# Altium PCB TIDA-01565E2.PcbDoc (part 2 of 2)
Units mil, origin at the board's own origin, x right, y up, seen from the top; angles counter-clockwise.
Board outline 1450 x 4000 mil, 4 copper layers (Top Layer L1, GND L2, Power L3, Bottom Layer L4), stack 62.4 mil thick; 92 components, 39 nets, 230 pads, 175 vias.
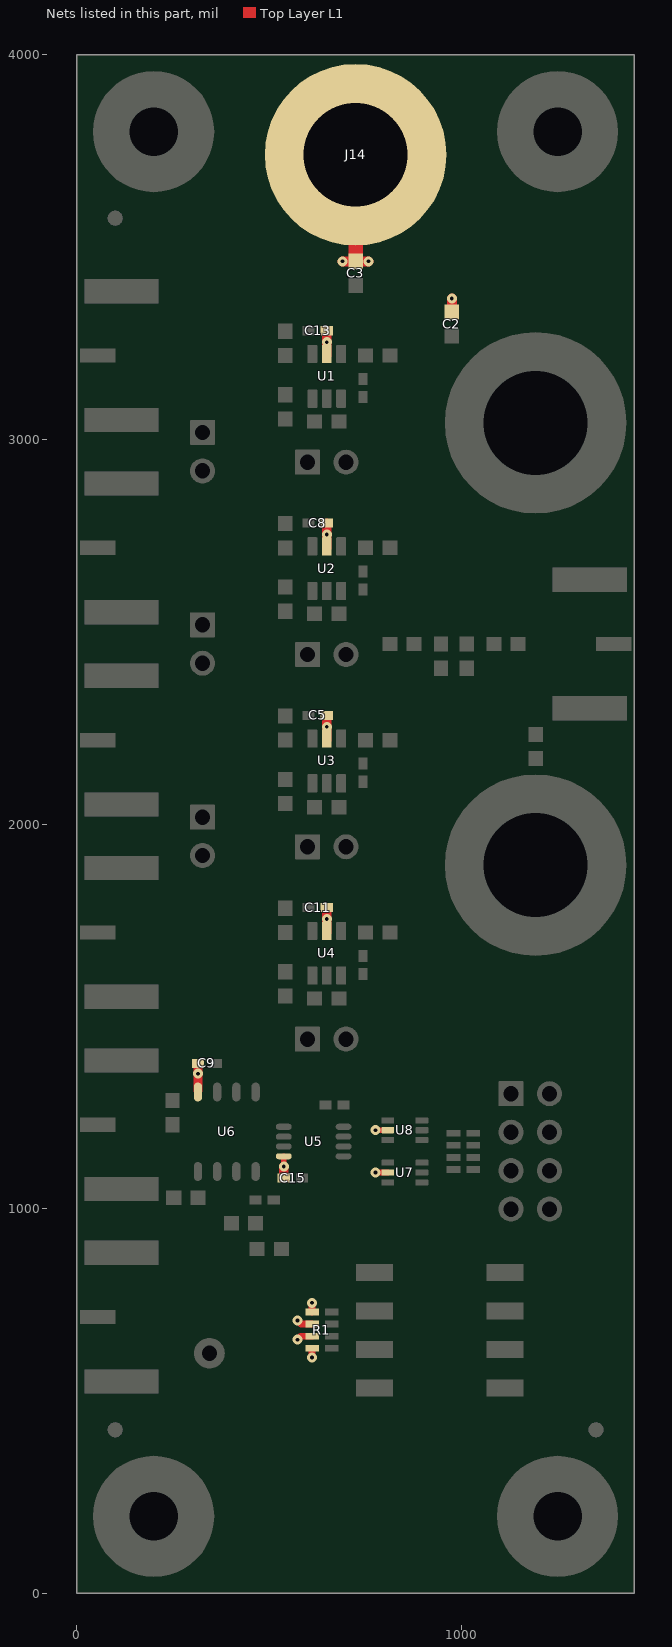
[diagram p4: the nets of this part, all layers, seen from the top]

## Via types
v1: diameter 26, hole 10, Top Layer L1 to Bottom Layer L4, tented both sides, 175 vias

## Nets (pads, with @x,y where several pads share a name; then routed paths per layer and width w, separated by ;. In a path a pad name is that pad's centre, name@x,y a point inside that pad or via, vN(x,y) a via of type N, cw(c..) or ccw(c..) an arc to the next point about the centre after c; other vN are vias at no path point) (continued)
VEE: C2.2 C3.1 C5.1 C8.1 C9.1 C11.1 C13.1 C15.2 J14.1 R1.5 R1.6 R1.7 R1.8 U1.2 U2.2 U3.2 U4.2 U5.4 U6.4 U7.2 U8.2 | length 957.6
  Top Layer L1 w15: v1(538.24,1109.69) U5.4@538.24,1136.02 ; v1(777.01,1093.81) U7.2@808.71,1093.81 ; v1(777.01,1203.81) U8.2@808.71,1203.81
  Top Layer L1 w17.72: v1(574.23,659.11) 583.37,668.25 R1.7@611.91,668.25 ; v1(574.23,708.89) 583.37,699.75 R1.6@611.91,699.75 ; v1(611.91,612.93) R1.8@611.91,636.76 ; R1.5@611.91,731.24 v1(611.91,755.07)
  Top Layer L1 w23.62: U6.4@315,1307.28 C9.1@314.96,1377.57 ; C15.2@538.24,1079.41 v1(538.24,1109.69) ; U4.2@650,1718 v1(650,1752.65) C11.1@650,1782.43 ; U3.2@650,2218 v1(650,2252.65) C5.1@650,2282.43 ; U2.2@650,2718 v1(650,2752.65) C8.1@650,2782.43 ; U1.2@650,3218 v1(650,3252.65) C13.1@650,3282.43
  Top Layer L1 w26: v1(691.33,3463) C3.1@725,3463 v1(758.67,3463) ; C2.2@975,3331.5 v1(975,3366.15)
  Top Layer L1 w37.4: C3.1@725,3463 J14.1@725,3740
  other v1: 315,1350.79
pads on no net: FID1.1 FID2.1 FID3.1 FID4.1 FID5.1 FID6.1 H5.0 H6.0 H7.0 H8.0 LBL1.0

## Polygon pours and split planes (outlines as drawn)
GND on Bottom Layer L4 "Bottom Layer L4-GND" (solid, remove dead copper, pour order 2): 20,20 20,3980 1429.99,3980 1430,20
GND on Top Layer L1 "Top Layer L4-GND" (solid, remove dead copper, pour order 4): 20,20 20,3980 1429.99,3980 1430,20
GND on GND L2 (split plane): 1429.9,20.1 20.1,20.1 20.1,3979.9 1429.9,3979.9
VCC on Power L3 (split plane): 230 vertices, not listed, extent 395.1,20.1 1429.9,3294.9
VEE on Power L3 (split plane): 205 vertices, not listed, extent 20.1,20.1 1429.9,3979.9

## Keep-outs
Keep-Out Layer:
  text ".Layer_Name" at 577,-858.49 h60

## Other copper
Top Layer L1:
  text ".Layer_Name" at 577,-858.49 h60
Bottom Layer L4:
  text ".Layer_Name" at 577,-858.49 h60
GND L2 (plane layer: these items are gaps in the copper):
  pour cut-out: 510.8,1519.35 510.8,1578.72 574.11,1578.72 574.11,1566.88 584.88,1566.88 584.88,1580.69 590.82,1590.69 590.55,1592.06 590.55,1627.41 591.48,1632.09 594.14,1636.07 598.11,1638.72 602.8,1639.65 622.4,1639.65 627.09,1638.72 631.06,1636.07 633.71,1632.09 634.64,1627.41 634.64,1592.06 634.37,1590.69 639.34,1582.41 641.28,1580.69 644.25,1580.69 644.25,1517.39 617.84,1517.39 617.84,1483.48 630.53,1483.48 635.19,1482.55 639.15,1479.91 641.79,1475.96 642.71,1471.29 642.71,1410.46 641.79,1405.57 639.15,1401.62 635.19,1398.97 630.53,1398.05 569.47,1398.05 564.81,1398.97 560.85,1401.62 558.21,1405.57 557.29,1410.23 557.29,1471.29 558.21,1475.96 560.85,1479.91 564.81,1482.55 569.47,1483.48 582.16,1483.48 582.16,1514.64 574.11,1519.35
  pour cut-out: 510.8,2019.35 510.8,2078.72 574.11,2078.72 574.11,2066.88 584.88,2066.88 584.88,2080.69 590.82,2090.69 590.55,2092.06 590.55,2127.41 591.48,2132.09 594.14,2136.07 598.11,2138.72 602.8,2139.65 622.4,2139.65 627.09,2138.72 631.06,2136.07 633.71,2132.09 634.64,2127.41 634.64,2092.06 634.37,2090.69 639.34,2082.41 641.28,2080.69 644.25,2080.69 644.25,2017.39 617.84,2017.39 617.84,1983.48 630.53,1983.48 635.19,1982.55 639.15,1979.91 641.79,1975.96 642.71,1971.29 642.71,1910.46 641.79,1905.57 639.15,1901.62 635.19,1898.97 630.53,1898.05 569.47,1898.05 564.81,1898.97 560.85,1901.62 558.21,1905.57 557.29,1910.23 557.29,1971.29 558.21,1975.96 560.85,1979.91 564.81,1982.55 569.47,1983.48 582.16,1983.48 582.16,2014.64 574.11,2019.35
  pour cut-out: 510.8,2519.35 510.8,2578.72 574.11,2578.72 574.11,2566.88 584.88,2566.88 584.88,2580.69 590.82,2590.69 590.55,2592.06 590.55,2627.41 591.48,2632.09 594.14,2636.07 598.11,2638.72 602.8,2639.65 622.4,2639.65 627.09,2638.72 631.06,2636.07 633.71,2632.09 634.64,2627.41 634.64,2592.06 634.37,2590.69 639.34,2582.41 641.28,2580.69 644.25,2580.69 644.25,2517.39 617.84,2517.39 617.84,2483.48 630.53,2483.48 635.19,2482.55 639.15,2479.91 641.79,2475.96 642.71,2471.29 642.71,2410.46 641.79,2405.57 639.15,2401.62 635.19,2398.97 630.53,2398.05 569.47,2398.05 564.81,2398.97 560.85,2401.62 558.21,2405.57 557.29,2410.23 557.29,2471.29 558.21,2475.96 560.85,2479.91 564.81,2482.55 569.47,2483.48 582.16,2483.48 582.16,2514.64 574.11,2519.35
  pour cut-out: 510.8,3019.35 510.8,3078.72 574.11,3078.72 574.11,3066.88 584.88,3066.88 584.88,3080.69 590.82,3090.69 590.55,3092.06 590.55,3127.41 591.48,3132.09 594.14,3136.07 598.11,3138.72 602.8,3139.65 622.4,3139.65 627.09,3138.72 631.06,3136.07 633.71,3132.09 634.64,3127.41 634.64,3092.06 634.37,3090.69 639.34,3082.41 641.28,3080.69 644.25,3080.69 644.25,3017.39 617.84,3017.39 617.84,2983.48 630.53,2983.48 635.19,2982.55 639.15,2979.91 641.79,2975.96 642.71,2971.29 642.71,2910.46 641.79,2905.57 639.15,2901.62 635.19,2898.98 630.53,2898.05 569.47,2898.05 564.81,2898.98 560.85,2901.62 558.21,2905.57 557.29,2910.23 557.29,2971.29 558.21,2975.96 560.85,2979.91 564.81,2982.55 569.47,2983.48 582.16,2983.48 582.16,3014.64 574.11,3019.35
  pour cut-out: 721.26,1700.16 721.26,1689.3 780.63,1689.3 780.63,1746.7 721.26,1746.7 721.26,1735.84 709.41,1735.84 708.52,1740.36 705.86,1744.33 701.89,1746.99 697.2,1747.92 677.6,1747.92 672.91,1746.99 668.94,1744.33 666.29,1740.36 665.36,1735.68 665.36,1700.32 666.29,1695.64 668.94,1691.67 672.91,1689.01 677.6,1688.08 697.2,1688.08 701.89,1689.01 705.86,1691.67 708.52,1695.64 709.41,1700.16
  pour cut-out: 721.26,2200.16 721.26,2189.3 780.63,2189.3 780.63,2246.7 721.26,2246.7 721.26,2235.84 709.41,2235.84 708.52,2240.36 705.86,2244.33 701.89,2246.99 697.2,2247.92 677.6,2247.92 672.91,2246.99 668.94,2244.33 666.29,2240.36 665.36,2235.68 665.36,2200.32 666.29,2195.64 668.94,2191.67 672.91,2189.01 677.6,2188.08 697.2,2188.08 701.89,2189.01 705.86,2191.67 708.52,2195.64 709.41,2200.16
  pour cut-out: 721.26,2700.16 721.26,2689.3 780.63,2689.3 780.63,2746.7 721.26,2746.7 721.26,2735.84 709.41,2735.84 708.52,2740.36 705.86,2744.33 701.89,2746.99 697.2,2747.92 677.6,2747.92 672.91,2746.99 668.94,2744.33 666.29,2740.36 665.36,2735.68 665.36,2700.32 666.29,2695.64 668.94,2691.67 672.91,2689.01 677.6,2688.08 697.2,2688.08 701.89,2689.01 705.86,2691.67 708.52,2695.64 709.41,2700.16
  pour cut-out: 721.26,3200.16 721.26,3189.3 780.63,3189.3 780.63,3246.7 721.26,3246.7 721.26,3235.84 709.41,3235.84 708.52,3240.36 705.86,3244.33 701.89,3246.99 697.2,3247.92 677.6,3247.92 672.91,3246.99 668.94,3244.33 666.29,3240.36 665.36,3235.68 665.36,3200.32 666.29,3195.64 668.94,3191.67 672.91,3189.01 677.6,3188.08 697.2,3188.08 701.89,3189.01 705.86,3191.67 708.52,3195.64 709.41,3200.16
  text "GND" at 700,50 h60
  text ".Layer_Name" at 577,-858.49 h60
Power L3 (plane layer: these items are gaps in the copper):
  pour cut-out: 721.26,3200.16 721.26,3189.3 780.63,3189.3 780.63,3246.7 721.26,3246.7 721.26,3235.84 709.41,3235.84 708.52,3240.36 705.86,3244.33 701.89,3246.99 697.2,3247.92 677.6,3247.92 672.91,3246.99 668.94,3244.33 666.29,3240.36 665.36,3235.68 665.36,3200.32 666.29,3195.64 668.94,3191.67 672.91,3189.01 677.6,3188.08 697.2,3188.08 701.89,3189.01 705.86,3191.67 708.52,3195.64 709.41,3200.16
  pour cut-out: 721.26,2700.16 721.26,2689.3 780.63,2689.3 780.63,2746.7 721.26,2746.7 721.26,2735.84 709.41,2735.84 708.52,2740.36 705.86,2744.33 701.89,2746.99 697.2,2747.92 677.6,2747.92 672.91,2746.99 668.94,2744.33 666.29,2740.36 665.36,2735.68 665.36,2700.32 666.29,2695.64 668.94,2691.67 672.91,2689.01 677.6,2688.08 697.2,2688.08 701.89,2689.01 705.86,2691.67 708.52,2695.64 709.41,2700.16
  pour cut-out: 721.26,2200.16 721.26,2189.3 780.63,2189.3 780.63,2246.7 721.26,2246.7 721.26,2235.84 709.41,2235.84 708.52,2240.36 705.86,2244.33 701.89,2246.99 697.2,2247.92 677.6,2247.92 672.91,2246.99 668.94,2244.33 666.29,2240.36 665.36,2235.68 665.36,2200.32 666.29,2195.64 668.94,2191.67 672.91,2189.01 677.6,2188.08 697.2,2188.08 701.89,2189.01 705.86,2191.67 708.52,2195.64 709.41,2200.16
  pour cut-out: 721.26,1700.16 721.26,1689.3 780.63,1689.3 780.63,1746.7 721.26,1746.7 721.26,1735.84 709.41,1735.84 708.52,1740.36 705.86,1744.33 701.89,1746.99 697.2,1747.92 677.6,1747.92 672.91,1746.99 668.94,1744.33 666.29,1740.36 665.36,1735.68 665.36,1700.32 666.29,1695.64 668.94,1691.67 672.91,1689.01 677.6,1688.08 697.2,1688.08 701.89,1689.01 705.86,1691.67 708.52,1695.64 709.41,1700.16
  pour cut-out: 510.8,3019.35 510.8,3078.72 574.11,3078.72 574.11,3066.88 584.88,3066.88 584.88,3080.69 590.82,3090.69 590.55,3092.06 590.55,3127.41 591.48,3132.09 594.14,3136.07 598.11,3138.72 602.8,3139.65 622.4,3139.65 627.09,3138.72 631.06,3136.07 633.71,3132.09 634.64,3127.41 634.64,3092.06 634.37,3090.69 639.34,3082.41 641.28,3080.69 644.25,3080.69 644.25,3017.39 617.84,3017.39 617.84,2983.48 630.53,2983.48 635.19,2982.55 639.15,2979.91 641.79,2975.96 642.71,2971.29 642.71,2910.46 641.79,2905.57 639.15,2901.62 635.19,2898.98 630.53,2898.05 569.47,2898.05 564.81,2898.98 560.85,2901.62 558.21,2905.57 557.29,2910.23 557.29,2971.29 558.21,2975.96 560.85,2979.91 564.81,2982.55 569.47,2983.48 582.16,2983.48 582.16,3014.64 574.11,3019.35
  pour cut-out: 510.8,2519.35 510.8,2578.72 574.11,2578.72 574.11,2566.88 584.88,2566.88 584.88,2580.69 590.82,2590.69 590.55,2592.06 590.55,2627.41 591.48,2632.09 594.14,2636.07 598.11,2638.72 602.8,2639.65 622.4,2639.65 627.09,2638.72 631.06,2636.07 633.71,2632.09 634.64,2627.41 634.64,2592.06 634.37,2590.69 639.34,2582.41 641.28,2580.69 644.25,2580.69 644.25,2517.39 617.84,2517.39 617.84,2483.48 630.53,2483.48 635.19,2482.55 639.15,2479.91 641.79,2475.96 642.71,2471.29 642.71,2410.46 641.79,2405.57 639.15,2401.62 635.19,2398.97 630.53,2398.05 569.47,2398.05 564.81,2398.97 560.85,2401.62 558.21,2405.57 557.29,2410.23 557.29,2471.29 558.21,2475.96 560.85,2479.91 564.81,2482.55 569.47,2483.48 582.16,2483.48 582.16,2514.64 574.11,2519.35
  pour cut-out: 510.8,2019.35 510.8,2078.72 574.11,2078.72 574.11,2066.88 584.88,2066.88 584.88,2080.69 590.82,2090.69 590.55,2092.06 590.55,2127.41 591.48,2132.09 594.14,2136.07 598.11,2138.72 602.8,2139.65 622.4,2139.65 627.09,2138.72 631.06,2136.07 633.71,2132.09 634.64,2127.41 634.64,2092.06 634.37,2090.69 639.34,2082.41 641.28,2080.69 644.25,2080.69 644.25,2017.39 617.84,2017.39 617.84,1983.48 630.53,1983.48 635.19,1982.55 639.15,1979.91 641.79,1975.96 642.71,1971.29 642.71,1910.46 641.79,1905.57 639.15,1901.62 635.19,1898.97 630.53,1898.05 569.47,1898.05 564.81,1898.97 560.85,1901.62 558.21,1905.57 557.29,1910.23 557.29,1971.29 558.21,1975.96 560.85,1979.91 564.81,1982.55 569.47,1983.48 582.16,1983.48 582.16,2014.64 574.11,2019.35
  pour cut-out: 510.8,1519.35 510.8,1578.72 574.11,1578.72 574.11,1566.88 584.88,1566.88 584.88,1580.69 590.82,1590.69 590.55,1592.06 590.55,1627.41 591.48,1632.09 594.14,1636.07 598.11,1638.72 602.8,1639.65 622.4,1639.65 627.09,1638.72 631.06,1636.07 633.71,1632.09 634.64,1627.41 634.64,1592.06 634.37,1590.69 639.34,1582.41 641.28,1580.69 644.25,1580.69 644.25,1517.39 617.84,1517.39 617.84,1483.48 630.53,1483.48 635.19,1482.55 639.15,1479.91 641.79,1475.96 642.71,1471.29 642.71,1410.46 641.79,1405.57 639.15,1401.62 635.19,1398.97 630.53,1398.05 569.47,1398.05 564.81,1398.97 560.85,1401.62 558.21,1405.57 557.29,1410.23 557.29,1471.29 558.21,1475.96 560.85,1479.91 564.81,1482.55 569.47,1483.48 582.16,1483.48 582.16,1514.64 574.11,1519.35
  lines w10: 637.5,0 637.5,834 390,834 390,1137 499.65,1137 499.65,1050.92 802,1050.92 802,1229 753,1229 753,1200 612.6,1200 612.6,1639.06 687.4,1713.87 687.4,1800 612.6,1874.8 612.6,2139.06 687.4,2213.87 687.4,2300 612.6,2374.8 612.6,2639.06 687.4,2713.87 687.4,2800 612.6,2874.8 612.6,3139.06 687.4,3213.87 687.4,3300 1450,3300
  text "VEE" at 425,50 h60
  text "VCC" at 900,50 h60
  text ".Layer_Name" at 577,-858.49 h60
Multi-Layer:
  pour cut-out: 721.26,3200.16 721.26,3189.3 780.63,3189.3 780.63,3246.7 721.26,3246.7 721.26,3235.84 709.41,3235.84 708.52,3240.36 705.86,3244.33 701.89,3246.99 697.2,3247.92 677.6,3247.92 672.91,3246.99 668.94,3244.33 666.29,3240.36 665.36,3235.68 665.36,3200.32 666.29,3195.64 668.94,3191.67 672.91,3189.01 677.6,3188.08 697.2,3188.08 701.89,3189.01 705.86,3191.67 708.52,3195.64 709.41,3200.16
  pour cut-out: 721.26,2700.16 721.26,2689.3 780.63,2689.3 780.63,2746.7 721.26,2746.7 721.26,2735.84 709.41,2735.84 708.52,2740.36 705.86,2744.33 701.89,2746.99 697.2,2747.92 677.6,2747.92 672.91,2746.99 668.94,2744.33 666.29,2740.36 665.36,2735.68 665.36,2700.32 666.29,2695.64 668.94,2691.67 672.91,2689.01 677.6,2688.08 697.2,2688.08 701.89,2689.01 705.86,2691.67 708.52,2695.64 709.41,2700.16
  pour cut-out: 721.26,2200.16 721.26,2189.3 780.63,2189.3 780.63,2246.7 721.26,2246.7 721.26,2235.84 709.41,2235.84 708.52,2240.36 705.86,2244.33 701.89,2246.99 697.2,2247.92 677.6,2247.92 672.91,2246.99 668.94,2244.33 666.29,2240.36 665.36,2235.68 665.36,2200.32 666.29,2195.64 668.94,2191.67 672.91,2189.01 677.6,2188.08 697.2,2188.08 701.89,2189.01 705.86,2191.67 708.52,2195.64 709.41,2200.16
  pour cut-out: 721.26,1700.16 721.26,1689.3 780.63,1689.3 780.63,1746.7 721.26,1746.7 721.26,1735.84 709.41,1735.84 708.52,1740.36 705.86,1744.33 701.89,1746.99 697.2,1747.92 677.6,1747.92 672.91,1746.99 668.94,1744.33 666.29,1740.36 665.36,1735.68 665.36,1700.32 666.29,1695.64 668.94,1691.67 672.91,1689.01 677.6,1688.08 697.2,1688.08 701.89,1689.01 705.86,1691.67 708.52,1695.64 709.41,1700.16
  pour cut-out: 510.8,3019.35 510.8,3078.72 574.11,3078.72 574.11,3066.88 584.88,3066.88 584.88,3080.69 590.82,3090.69 590.55,3092.06 590.55,3127.41 591.48,3132.09 594.14,3136.07 598.11,3138.72 602.8,3139.65 622.4,3139.65 627.09,3138.72 631.06,3136.07 633.71,3132.09 634.64,3127.41 634.64,3092.06 634.37,3090.69 639.34,3082.41 641.28,3080.69 644.25,3080.69 644.25,3017.39 617.84,3017.39 617.84,2983.48 630.53,2983.48 635.19,2982.55 639.15,2979.91 641.79,2975.96 642.71,2971.29 642.71,2910.46 641.79,2905.57 639.15,2901.62 635.19,2898.98 630.53,2898.05 569.47,2898.05 564.81,2898.98 560.85,2901.62 558.21,2905.57 557.29,2910.23 557.29,2971.29 558.21,2975.96 560.85,2979.91 564.81,2982.55 569.47,2983.48 582.16,2983.48 582.16,3014.64 574.11,3019.35
  pour cut-out: 510.8,2519.35 510.8,2578.72 574.11,2578.72 574.11,2566.88 584.88,2566.88 584.88,2580.69 590.82,2590.69 590.55,2592.06 590.55,2627.41 591.48,2632.09 594.14,2636.07 598.11,2638.72 602.8,2639.65 622.4,2639.65 627.09,2638.72 631.06,2636.07 633.71,2632.09 634.64,2627.41 634.64,2592.06 634.37,2590.69 639.34,2582.41 641.28,2580.69 644.25,2580.69 644.25,2517.39 617.84,2517.39 617.84,2483.48 630.53,2483.48 635.19,2482.55 639.15,2479.91 641.79,2475.96 642.71,2471.29 642.71,2410.46 641.79,2405.57 639.15,2401.62 635.19,2398.97 630.53,2398.05 569.47,2398.05 564.81,2398.97 560.85,2401.62 558.21,2405.57 557.29,2410.23 557.29,2471.29 558.21,2475.96 560.85,2479.91 564.81,2482.55 569.47,2483.48 582.16,2483.48 582.16,2514.64 574.11,2519.35
  pour cut-out: 510.8,2019.35 510.8,2078.72 574.11,2078.72 574.11,2066.88 584.88,2066.88 584.88,2080.69 590.82,2090.69 590.55,2092.06 590.55,2127.41 591.48,2132.09 594.14,2136.07 598.11,2138.72 602.8,2139.65 622.4,2139.65 627.09,2138.72 631.06,2136.07 633.71,2132.09 634.64,2127.41 634.64,2092.06 634.37,2090.69 639.34,2082.41 641.28,2080.69 644.25,2080.69 644.25,2017.39 617.84,2017.39 617.84,1983.48 630.53,1983.48 635.19,1982.55 639.15,1979.91 641.79,1975.96 642.71,1971.29 642.71,1910.46 641.79,1905.57 639.15,1901.62 635.19,1898.97 630.53,1898.05 569.47,1898.05 564.81,1898.97 560.85,1901.62 558.21,1905.57 557.29,1910.23 557.29,1971.29 558.21,1975.96 560.85,1979.91 564.81,1982.55 569.47,1983.48 582.16,1983.48 582.16,2014.64 574.11,2019.35
  pour cut-out: 510.8,1519.35 510.8,1578.72 574.11,1578.72 574.11,1566.88 584.88,1566.88 584.88,1580.69 590.82,1590.69 590.55,1592.06 590.55,1627.41 591.48,1632.09 594.14,1636.07 598.11,1638.72 602.8,1639.65 622.4,1639.65 627.09,1638.72 631.06,1636.07 633.71,1632.09 634.64,1627.41 634.64,1592.06 634.37,1590.69 639.34,1582.41 641.28,1580.69 644.25,1580.69 644.25,1517.39 617.84,1517.39 617.84,1483.48 630.53,1483.48 635.19,1482.55 639.15,1479.91 641.79,1475.96 642.71,1471.29 642.71,1410.46 641.79,1405.57 639.15,1401.62 635.19,1398.97 630.53,1398.05 569.47,1398.05 564.81,1398.97 560.85,1401.62 558.21,1405.57 557.29,1410.23 557.29,1471.29 558.21,1475.96 560.85,1479.91 564.81,1482.55 569.47,1483.48 582.16,1483.48 582.16,1514.64 574.11,1519.35

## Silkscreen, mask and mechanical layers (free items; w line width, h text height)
Top Overlay:
  text "'.PRJ_Number'.PCB_Rev" at 951,3506 h40
  text ".Layer_Name" at 577,-858.49 h60
Bottom Overlay:
  text ".Layer_Name" at 577,-858.49 h60
Top Paste:
  text ".Layer_Name" at 577,-858.49 h60
Bottom Paste:
  text ".Layer_Name" at 577,-858.49 h60
Top Solder:
  text ".Layer_Name" at 577,-858.49 h60
  text ".Layer_Name" at 577,-858.49 h60
Bottom Solder:
  text ".Layer_Name" at 577,-858.49 h60
Drill Guide:
  text ".Layer_Name" at 577,-858.49 h60
M1 Board Outline:
  the board outline again, w10
  text ".Layer_Name" at 577,-858.49 h60
M2 Board Dimensions:
  rectangle: 125,-400 500,-275
  rectangle: 0,-275 125,-150
  lines w7: 0,-275 1000,-275 ; 125,-400 125,-150 ; 250,-400 250,-150 ; 500,-400 500,-150 ; 750,-400 750,-150 ; 0,-400 0,-150 1000,-150 1000,-400 0,-400
  text ".Layer_Name" at 577,-858.49 h60
M3 3D STEP Top:
  text ".Layer_Name" at 577,-858.49 h60
M4 3D STEP Bottom:
  text ".Layer_Name" at 577,-858.49 h60
M5 Assembly Top:
  lines w10: -292,-930.17 6308,-930.17 ; -292,-726.83 6310,-726.83 ; -292,-523.5 -292,-1133.5 3713,-1133.5 6310,-1133.5 6310,-523.5 -291.5,-523.5 -291.5,-1133.5 1284,-1133.5 ; 2173,-1133.5 2173,-523.5 ; 3440,-726.83 3440,-523.5 ; 4280,-726.83 4280,-523.5 ; 4902,-1140 4902,-937.17
  text "COMPONENTS MARKED 'DNP' SHOULD NOT BE POPULATED." at 1153.5,-318.5 h60
  text "ASSEMBLY VARIANT:" at 1153,-434 h60
  text ".VariantName" at 2189,-434 h60
  text "PCB VIEWED FROM TOP SIDE" at -228.5,-655.67 h60
  text "BOARD #:" at 2248,-655.67 h60
  text ".PRJ_Number" at 2793.5,-655.67 h60
  text "REV:" at 3638,-655.67 h60
  text ".PCB_Rev" at 3929.5,-655.67 h60
  text "SVN REV:" at 4476,-655.67 h60
  text ".VersionControl_RevNumber" at 4982,-655.67 h60
  text "TID #:" at 2248,-859 h60
  text ".TID" at 2793.5,-859 h60
  text "PLOT NAME =" at -228.5,-1064.34 h60
  text ".plot_File_Name" at 577,-1064.34 h60
  text "GENERATED    :" at 2250,-1064.34 h60
  text ".Print_Date" at 3119.5,-1064.34 h60
  text ".Print_Time" at 3848.5,-1064.34 h60
  text "TEXAS INSTRUMENTS" at 5113,-1064.34 h60
M6 Assembly Bottom:
  lines w10: -292.5,-727.33 6309.5,-727.33 ; -290.5,-930.67 6309.5,-930.67 ; 1115.5,-1140.5 1115.5,-937.67 ; 1737.5,-727.33 1737.5,-524 ; 2577.5,-727.33 2577.5,-524 ; 3844.5,-1134 3844.5,-524 ; 4733.5,-1134 6309,-1134 6309,-524 -292.5,-524 -292.5,-1134 2304.5,-1134 6309.5,-1134 6309.5,-524
  text "COMPONENTS MARKED 'DNP' SHOULD NOT BE POPULATED." at 6102,-318 h60
  text ".VariantName" at 5058,-434 h60
  text "ASSEMBLY VARIANT:" at 6097,-434 h60
  text ".VersionControl_RevNumber" at 1035.5,-656.17 h60
  text "SVN REV:" at 1541.5,-656.17 h60
  text ".PCB_Rev" at 2088,-656.17 h60
  text "REV:" at 2379.5,-656.17 h60
  text ".PRJ_Number" at 3224,-656.17 h60
  text "BOARD #:" at 3769.5,-656.17 h60
  text "PCB VIEWED FROM BOTTOM SIDE" at 6246,-656.17 h60
  text ".TID" at 3224,-859.5 h60
  text "TID #:" at 3769.5,-859.5 h60
  text "TEXAS INSTRUMENTS" at 904.5,-1064.84 h60
  text ".Print_Time" at 2169,-1064.84 h60
  text ".Print_Date" at 2898,-1064.84 h60
  text "GENERATED    :" at 3767.5,-1064.84 h60
  text ".plot_File_Name" at 5440.5,-1064.84 h60
  text "PLOT NAME =" at 6246,-1064.84 h60
M9 Title Sheet:
  drawing of 57 lines, arcs and shapes, not listed
  text "1" at 739.84,8036.5 h70
  text "2" at 3235.5,8036.5 h70
  text "3" at 5724.84,8036.5 h70
  text "4" at 8231.51,8036.5 h70
  text "5" at 10730.5,8036.5 h70
  text "6" at 13235.5,8036.5 h70
  text "A" at -416.5,6893.5 h70
  text "A" at 14383.5,6893.5 h70
  text "B" at -416.5,4513.5 h70
  text "B" at 14383.5,4513.5 h70
  text "C" at -416.5,2138.5 h70
  text "C" at 14383.5,2138.5 h70
  text "PROJECT TITLE:" at 11343.5,277.5 h45
  text ".PRJ_Title" at 11393.5,144.17 h70
  text "DESIGNED FOR:" at 11343.5,-23.5 h45
  text ".PRJ_Customer" at 11393.5,-163.5 h70
  text "D" at -416.5,-231.5 h70
  text "D" at 14383.5,-231.5 h70
  text "FILE NAME:" at 11343.5,-323.5 h45
  text ".PCB_File_Name_No_Path" at 11393.5,-443.5 h70
  text "Texas Instruments (TI) and/or its licensors do not warrant the accuracy or completeness of this specification" at 6374,-605.34 h45
  text "ENGINEER:" at 11343.5,-613.5 h45
  text "LAYOUT BY:" at 12848.5,-613.5 h45
  text "or any information contained therein. TI and/or its licensors do not warrant that this design will meet" at 6329.01,-718 h45
  text ".PRJ_Engineer" at 11393.5,-768.49 h70
  text ".PCB_Layout" at 12899,-768.49 h70
  text "the specifications, will be suitable for your application or fit for any particular purpose, or will operate in" at 6329.01,-830.67 h45
  text ".Layer_Name" at 577,-858.49 h60
  text "ALTIUM DESIGNER VERSION:" at 12848.5,-923.5 h45
  text "an implementation. TI and/or its licensors do not warrant that the design is production worthy. You should" at 6329.01,-943.33 h45
  text "completely validate and test your design implementation to confirm the system functionality for your application." at 6374,-1056 h45
  text ".print_Scale" at 11393.5,-1056.83 h70
  text ".Application_BuildNumber" at 12899,-1056.83 h70
  text "1" at 739.84,-1263.5 h70
  text "2" at 3235.5,-1263.5 h70
  text "3" at 5724.84,-1263.5 h70
  text "4" at 8231.51,-1263.5 h70
  text "5" at 10730.5,-1263.5 h70
  text "6" at 13235.5,-1263.5 h70
M10 Fab Notes:
  drawing of 173 lines, arcs and shapes, not listed
  text "DESIGN INFORMATION" at 12378.02,6201 h60
  text "MIN. TRACK WIDTH:" at 11733.46,6021 h60
  text "8" at 12829.7,6021 h60
  text "MIL" at 12984.46,6021 h60
  text "MIN. CLEARANCE:" at 11733.46,5889 h60
  text "0.2" at 12769.7,5889 h60
  text "mm" at 12984.46,5889 h60
  text "MIN. VIA PAD SIZE:" at 11733.46,5757 h60
  text "24" at 12799.71,5757 h60
  text "MIL" at 12984.46,5757 h60
  text "0.05mm (2MIL)" at 12428.46,5615.29 h60
  text "MINIMUM ANNULAR RING" at 11404.23,5611 h60
  text "EXTERNAL" at 13136.46,5611 h60
  text "PER" at 11604.23,5493 h60
  text "IPC-D-275 CLASS 2 LEVEL C" at 11824.23,5493 h60
  text "MIL, HOLES" at 13312.46,5380.71 h60
  text "+/-" at 12920,5380 h60
  text "+/-" at 13774,5380 h60
  text "REGISTRATION TOLERANCES:" at 11404.23,5375 h60
  text "METAL" at 12604,5375 h60
  text "5" at 13180.2,5375 h60
  text "3" at 14013.2,5375 h60
  text "MIL" at 14129.46,5375 h60
  text "+/-" at 13774,5262 h60
  text "HOLE SIZE TOLERANCE (UNLESS OTHERWISE SPECIFIED):" at 11404.23,5257 h60
  text "3" at 14013.2,5257 h60
  text "MIL" at 14129.46,5257 h60
  text "MATERIAL:" at 11329.46,5047.54 h60
  text "FR-4 High Tg" at 12315.9,4907.21 h60
  text "FR-408" at 11750.46,4898.64 h60
  text "OTHER" at 13238.46,4898.64 h60
  text "X" at 12161,4895 h60
  text "62 MIL (1.6mm) +/-10%" at 12070.56,4735.92 h60
  text "THICKNESS:" at 11404.23,4731.64 h60
  text "X" at 11942.4,4731.64 h60
  text "OTHER" at 13355.46,4731.64 h60
  text "TOLERANCE:" at 11404.23,4573.64 h60
  text "X" at 12243.53,4573.64 h60
  text "ANSI IPC-6012 TYPE 3 CLASS 2" at 12430.48,4573.64 h60
  text "OTHER +/-" at 12430.46,4417.64 h60
  text "BOW & TWIST:" at 11404.23,4260.64 h60
  text "X" at 12243.53,4260.64 h60
  text "ANSI IPC-6012 TYPE 3 CLASS 2" at 12430.48,4260.64 h60
  text "OTHER +/-" at 12430.46,4102.13 h60
  text "DRILLING:" at 11329.46,3963.64 h60
  text "REFERENCE:" at 11404.23,3846.64 h60
  text "X" at 12052.46,3846.64 h60
  text "AS SHOWN" at 12239.46,3846.64 h60
  text "X" at 12953.46,3846.64 h60
  text "NC_DRILL FILES" at 13090.46,3846.64 h60
  text "PTH COPPER THICKNESS:" at 11404.23,3688.64 h60
  text "X" at 12534.46,3688.64 h60
  text "20-30 um" at 12671.46,3688.64 h60
  text "OTHER" at 13388.46,3688.64 h60
  text "BOARD FINISH:" at 11329.46,3529.64 h60
  text "SILKSCREEN:" at 11484.68,3411.64 h60
  text "X" at 12433.46,3411.64 h60
  text "TOP" at 12559.46,3411.64 h60
  text "BOTTOM" at 13070.46,3411.64 h60
  text "SILKSCREEN COLOR:" at 11484.68,3244.64 h60
  text "X" at 12432.42,3244.64 h60
  text "WHITE" at 12559.46,3244.64 h60
  text "OTHER" at 13070.46,3244.64 h60
  text "X" at 12563.42,3085.44 h60
  text "GREEN" at 12690.46,3085.44 h60
  text "OTHER" at 13308.46,3085.44 h60
  text "SOLDER RESIST COLOR:" at 11484.68,3074.64 h60
  text "X" at 12563.42,2915.44 h60
  text "MATTE" at 12690.46,2915.44 h60
  text "SEMI-GLOSS" at 13308,2914.8 h60
  text "IMMERSION GOLD (ENIG)" at 12390.46,2726.92 h60
  text "ENEPIG" at 13728,2723.64 h60
  text "SURFACE FINISH:" at 11329.46,2722.64 h60
  text "X" at 12203.51,2722.64 h60
  text "IMM. TIN/SILVER OR EQUIV" at 11659,2565.64 h60
  text "OTHER" at 13090.46,2565.64 h60
  text "ARRAY/PANEL:" at 11329.46,2386.64 h60
  text "CUT AND TRIM PER M1 BOARD OUTLINE" at 12390.46,2382.35 h60
  text "N.C. ROUTE" at 12390.46,2230.64 h60
  text "X" at 13069.46,2230.64 h60
  text "V. SCORE" at 13256.46,2230.64 h60
  text "CERTIFICATION:" at 11329.46,2093.64 h60
  text "MATERIALS AND WORKMANSHIP FOR ALL PCBS" at 12054.46,2093.64 h60
  text "TO MEET OR EXCEED THE REQUIREMENTS OF:" at 12054.46,1995.64 h60
  text "X" at 11680.96,1859.13 h60
  text "ANSI IPC-A-600F CLASS ->" at 11819.96,1859.13 h60
  text "X" at 13459.02,1859.13 h60
  text "2" at 13577.96,1859.14 h60
  text "1" at 13262.96,1857.64 h60
  text "3" at 13931.96,1857.64 h60
  text "X" at 12495.02,1699.64 h60
  text "RoHS" at 12631.96,1699.64 h60
  text "OTHER" at 13276.36,1699.64 h60
  text "PER ORDER" at 13673.42,1699.64 h60
  text "ALL BOARDS MUST MEET OR EXCEED UL94-V0 REQUIREMENTS." at 11357,1534 h60
  text "PCB MUST BEAR THE UL94V-0 UL REGISTERED MATERIAL ID NUMBER" at 11357,1414 h60
  text "ADDITIONAL REQUIREMENTS:" at 11329.46,1240.64 h60
  text "MICROSECTION:" at 11404.23,1125.64 h60
  text "YES" at 12309.96,1125.64 h60
  text "REQUIRED" at 13171.46,969.49 h60
  text "BARE BOARD ELEC. TEST:" at 11404.23,966.64 h60
  text "NONE" at 12709.96,966.64 h60
  text "X" at 13044.46,966.64 h60
  text "PER ORDER" at 13763.46,966.64 h60
  text ".Layer_Name" at 577,-858.49 h60
M11 Gerber Information:
  lines w10: -292,-930.17 6308,-930.17 ; -292,-726.83 6310,-726.83 ; -292,-523.5 -292,-1133.5 3713,-1133.5 6310,-1133.5 6310,-523.5 -291.5,-523.5 -291.5,-1133.5 1284,-1133.5 ; 2173,-1133.5 2173,-523.5 ; 3440,-726.83 3440,-523.5 ; 4280,-726.83 4280,-523.5 ; 4902,-1140 4902,-937.17
  text "ALL ARTWORK VIEWED FROM TOP SIDE" at -228.5,-655.67 h60
  text "BOARD #:" at 2248,-655.67 h60
  text ".PRJ_Number" at 2793.5,-655.67 h60
  text "REV:" at 3638,-655.67 h60
  text ".PCB_Rev" at 3929.5,-655.67 h60
  text "SVN REV:" at 4476,-655.67 h60
  text ".VersionControl_RevNumber" at 4982,-655.67 h60
  text "LAYER NAME =" at -228.5,-858.49 h60
  text "TID #:" at 2248,-859 h60
  text ".TID" at 2793.5,-859 h60
  text "PLOT NAME =" at -228.5,-1064.34 h60
  text ".plot_File_Name" at 577,-1064.34 h60
  text "GENERATED    :" at 2250,-1064.34 h60
  text ".Print_Date" at 3119.5,-1064.34 h60
  text ".Print_Time" at 3848.5,-1064.34 h60
  text "TEXAS INSTRUMENTS" at 5113,-1064.34 h60
M12 Stackup:
  drawing of 295 lines, arcs and shapes, not listed
  text "Layer" at 9667.5,7830 h60
  text "Name" at 10077.41,7830 h60
  text "Material" at 11077.13,7830 h60
  text "Thickness" at 11936.9,7830 h60
  text "Constant" at 12586.74,7830 h60
  text "Board Layer Stack" at 13156.6,7830 h60
  text "1" at 9667.5,7710 h60
  text "Top Overlay" at 10077.41,7710 h60
  text "2" at 9667.5,7590 h60
  text "Top Solder" at 10077.41,7590 h60
  text "Solder Resist" at 11077.13,7590 h60
  text "0.40mil" at 11936.9,7590 h60
  text "3.5" at 12586.74,7590 h60
  text "3" at 9667.5,7470 h60
  text "Top Layer L1" at 10077.41,7470 h60
  text "Copper" at 11077.13,7470 h60
  text "1.40mil" at 11936.9,7470 h60
  text "4" at 9667.5,7350 h60
  text "Dielectric 1" at 10077.41,7350 h60
  text "FR-4 High Tg" at 11077.13,7350 h60
  text "8.40mil" at 11936.9,7350 h60
  text "4.6" at 12586.74,7350 h60
  text "5" at 9667.5,7230 h60
  text "GND L2" at 10077.41,7230 h60
  text "Copper" at 11077.13,7230 h60
  text "1.40mil" at 11936.9,7230 h60
  text "6" at 9667.5,7110 h60
  text "Dielectric 2" at 10077.41,7110 h60
  text "FR-4 High Tg" at 11077.13,7110 h60
  text "40.00mil" at 11936.9,7110 h60
  text "4.6" at 12586.74,7110 h60
  text "7" at 9667.5,6990 h60
  text "Power L3" at 10077.41,6990 h60
  text "Copper" at 11077.13,6990 h60
  text "1.40mil" at 11936.9,6990 h60
  text "8" at 9667.5,6870 h60
  text "Dielectric 3" at 10077.41,6870 h60
  text "FR-4 High Tg" at 11077.13,6870 h60
  text "8.40mil" at 11936.9,6870 h60
  text "4.6" at 12586.74,6870 h60
  text "9" at 9667.5,6750 h60
  text "Bottom Layer L4" at 10077.41,6750 h60
  text "Copper" at 11077.13,6750 h60
  text "1.40mil" at 11936.9,6750 h60
  text "10" at 9667.5,6630 h60
  text "Bottom Solder" at 10077.41,6630 h60
  text "Solder Resist" at 11077.13,6630 h60
  text "0.40mil" at 11936.9,6630 h60
  text "3.5" at 12586.74,6630 h60
  text "11" at 9667.5,6510 h60
  text "Bottom Overlay" at 10077.41,6510 h60
  text ".Layer_Name" at 577,-858.49 h60
M13 Component Bodies Top:
  text ".Layer_Name" at 577,-858.49 h60
M14 Component Bodies Bottom:
  text ".Layer_Name" at 577,-858.49 h60
M15 Courtyards Top:
  text ".Layer_Name" at 577,-858.49 h60
M16 Courtyards Bottom:
  text ".Layer_Name" at 577,-858.49 h60
Drill Drawing:
  circle w10: c1833.82,317.02 r27.67
  lines w10: 1806.16,220.18 1861.49,220.18 1833.82,164.85 1806.16,220.18 ; 1806.16,427.68 1819.99,427.68 1833.82,413.85 1847.66,427.68 1861.49,427.68 1847.66,441.52 1861.49,455.35 1847.66,455.35 1833.82,469.18 1819.99,455.35 1806.16,455.35 1819.99,441.52 1806.16,427.68 ; 1806.16,538.35 1833.82,552.18 1861.49,538.35 1847.66,566.02 1861.49,593.68 1833.82,579.85 1806.16,593.68 1819.99,566.02 1806.16,538.35
  lines w12: 1756,127.5 5141.34,127.5 ; 1756,625.5 5141.34,625.5 ; 2094.01,3 2094.01,750 ; 2426.17,3 2426.17,750 ; 3062.65,3 3062.65,750 ; 3321.85,3 3321.85,750 ; 3697.09,3 3697.09,750 ; 4574.79,3 4574.79,750 ; 1756,3 5141.34,3 5141.34,750 1756,750 1756,3
  text "Symbol" at 1830.7,662.85 h72
  text "Quantity" at 2131.36,662.85 h72
  text "Finished Hole Size" at 2463.52,662.85 h72
  text "Plated" at 3100,662.85 h72
  text "Hole Type" at 3359.2,662.85 h72
  text "Drill Layer Pair" at 3734.44,662.85 h72
  text "Hole Tolerance" at 4612.14,662.85 h72
  text "175" at 2131.36,538.35 h60
  text "10.00mil (0.254mm)" at 2463.52,538.35 h60
  text "PTH" at 3100,538.35 h60
  text "Round" at 3359.2,538.35 h60
  text "Top Layer L1 - Bottom Layer L4" at 3734.44,538.35 h60
  text "23" at 2131.36,413.85 h60
  text "40.00mil (1.016mm)" at 2463.52,413.85 h60
  text "PTH" at 3100,413.85 h60
  text "Round" at 3359.2,413.85 h60
  text "Top Layer L1 - Bottom Layer L4" at 3734.44,413.85 h60
  text "4" at 2131.36,289.35 h60
  text "125.98mil (3.200mm)" at 2463.52,289.35 h60
  text "PTH" at 3100,289.35 h60
  text "Round" at 3359.2,289.35 h60
  text "Top Layer L1 - Bottom Layer L4" at 3734.44,289.35 h60
  text "3" at 2131.36,164.85 h60
  text "270.00mil (6.858mm)" at 2463.52,164.85 h60
  text "PTH" at 3100,164.85 h60
  text "Round" at 3359.2,164.85 h60
  text "Top Layer L1 - Bottom Layer L4" at 3734.44,164.85 h60
  text "205 Total" at 2131.36,40.35 h60
  text ".Layer_Name" at 577,-858.49 h60
M17 Embedded Cavity:
  text ".Layer_Name" at 577,-858.49 h60
M18 Embedded Assembly:
  text ".Layer_Name" at 577,-858.49 h60
M19 Embedded Keepout:
  text ".Layer_Name" at 577,-858.49 h60

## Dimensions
0,0 to 1450,0 on M2 Board Dimensions
0,0 to 0,4000 on M2 Board Dimensions
0,-400 to 1000,-400 on M2 Board Dimensions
